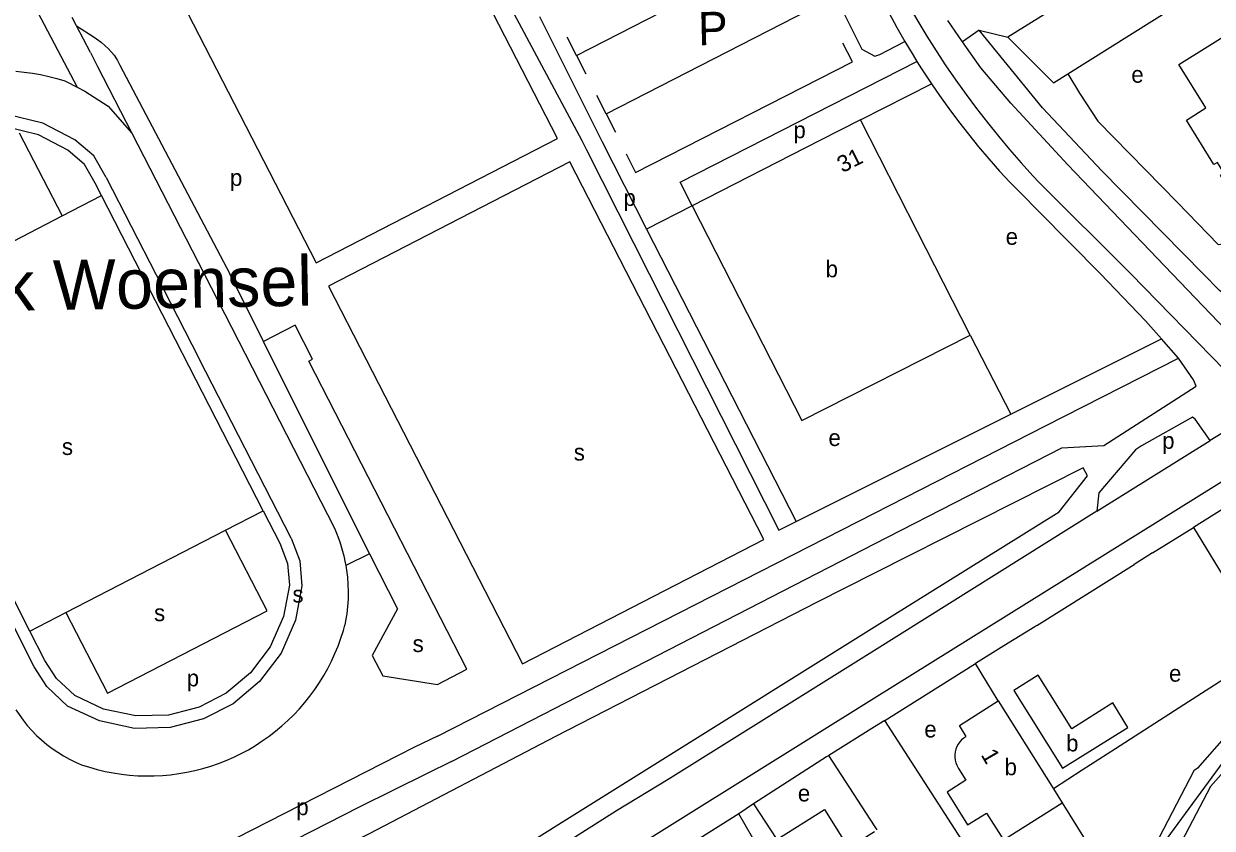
# Model space of a CAD drawing. Extents: x 158848 to 160613, y 385889 to 387762.
# Drawn here: x 159618.1 to 159904.5, y 387116.4 to 387310.2 of the extents above; entities that cross this region are included whole.
import ezdxf

# ---------------------------------------------------------------- set-up
doc = ezdxf.new("R2010")
doc.units = 0
for name, color, linetype in [('BLT_Basislijn', 7, 'Continuous'), ('BLT_Bebouwing', 7, 'Continuous'), ('BLT_Centroide', 7, 'Continuous'), ('BLT_Hoogspanningsmast_en_leidingen', 7, 'Continuous'), ('BLT_Huisnummer', 7, 'Continuous'), ('BLT_Sport_parknaam', 7, 'Continuous'), ('BLT_Tekst_parkeren', 7, 'Continuous')]:
    doc.layers.add(name, color=color, linetype=linetype)

msp = doc.modelspace()

# ---------------------------------------------------------------- linework, layer by layer
at = {"layer": 'BLT_Basislijn'}
for p, q in [((159751.28, 387302.61), (159803.28, 387329.21)), ((159619.88, 387316.11), (159630.91, 387294.99)), ((159758.44, 387288.54), (159810.48, 387315.16)), ((159630.76, 387309.75), (159629.73, 387311.77)), ((159844.35, 387305.87), (159840.78, 387310.98)), ((159848.34, 387308.65), (159844.35, 387305.87)), ((159848.34, 387308.65), (159855.27, 387306.97)), ((159751.28, 387302.61), (159749.02, 387307.04)), ((159634.14, 387303.34), (159635.87, 387299.97)), ((159751.28, 387302.61), (159753.54, 387298.17)), ((159635.87, 387299.97), (159644.12, 387283.9)), ((159628.25, 387296.36), (159630.91, 387294.99)), ((159819.77, 387287.1), (159836.83, 387295.76)), ((159758.44, 387288.54), (159756.18, 387292.97)), ((159758.44, 387288.54), (159760.69, 387284.11)), ((159616.97, 387283.94), (159627.32, 387263.93)), ((159644.12, 387283.9), (159661.52, 387250)), ((159752.58, 387282.07), (159753.71, 387279.83)), ((159757.47, 387281.77), (159768.2, 387260.77)), ((159753.71, 387279.83), (159768.79, 387250)), ((159637.95, 387273.18), (159649.96, 387249.77)), ((159858.3, 387269.48), (159855.76, 387272.05)), ((159862.71, 387272.05), (159884.93, 387250)), ((159627.32, 387263.93), (159636.8, 387268.84)), ((159675.76, 387192.89), (159636.8, 387268.84)), ((159862.75, 387264.98), (159858.3, 387269.48)), ((159779.19, 387266.39), (159768.2, 387260.77)), ((159877.59, 387250), (159862.75, 387264.98)), ((159591.19, 387245.23), (159627.32, 387263.93)), ((159768.2, 387260.77), (159804.24, 387190.31)), ((159649.96, 387249.77), (159660.26, 387229.68)), ((159661.52, 387250), (159692.96, 387188.72)), ((159675.88, 387233.68), (159667.73, 387250)), ((159619.56, 387163.91), (159580.91, 387239.91)), ((159701.43, 387182.51), (159675.88, 387233.68)), ((159846.17, 387235.22), (159855.95, 387216.16)), ((159855.95, 387216.16), (159892.27, 387234.31)), ((159896.37, 387229.67), (159892.27, 387234.31)), ((159682.5, 387186.32), (159660.26, 387229.68)), ((159864.37, 387213.35), (159896.37, 387229.67)), ((159804.24, 387190.31), (159855.95, 387216.16)), ((159823.15, 387192.34), (159864.37, 387213.35)), ((159876.74, 387192.8), (159903.99, 387209.8)), ((159620.56, 387155.33), (159598.93, 387198.22)), ((159910.62, 387195.56), (159899.97, 387188.9)), ((159666.71, 387188.22), (159675.76, 387192.89)), ((159799.49, 387180.27), (159823.15, 387192.34)), ((159876.74, 387192.8), (159823.15, 387159.28)), ((159628.23, 387168.38), (159666.71, 387188.22)), ((159676.71, 387168.83), (159666.71, 387188.22)), ((159890.12, 387182.75), (159899.97, 387188.9)), ((159721.13, 387132.51), (159823.15, 387184.9)), ((159701.43, 387182.51), (159695.68, 387179.71)), ((159890.12, 387182.75), (159885.74, 387179.97)), ((159717.79, 387138.6), (159799.49, 387180.27)), ((159862.26, 387165.23), (159885.74, 387179.97)), ((159619.56, 387163.91), (159628.23, 387168.38)), ((159628.23, 387168.38), (159638.23, 387148.99)), ((159638.23, 387148.99), (159676.71, 387168.83)), ((159854.32, 387160.35), (159847.45, 387156.09)), ((159852.91, 387147.1), (159847.45, 387156.09)), ((159897.67, 387146.13), (159881.2, 387135.53)), ((159825.6, 387142.4), (159823.15, 387140.87)), ((159852.89, 387100.09), (159825.6, 387142.4)), ((159717.79, 387138.6), (159712.26, 387135.93)), ((159823.15, 387140.87), (159812.13, 387133.98)), ((159712.26, 387135.93), (159645.73, 387102.09)), ((159823.15, 387117.04), (159812.13, 387133.98)), ((159881.2, 387135.53), (159873.2, 387130.38)), ((159721.13, 387132.51), (159715.29, 387129.57)), ((159873.2, 387130.38), (159866.25, 387125.91)), ((159793.99, 387122.27), (159790.39, 387119.92)), ((159793.99, 387122.27), (159799.55, 387113.71)), ((159790.39, 387119.92), (159778.96, 387112.63)), ((159823.79, 387116.06), (159823.15, 387117.04))]:
    msp.add_line(p, q, dxfattribs=at)
msp.add_lwpolyline([(159746.73, 387282.61), (159698.67, 387376), (159640.5, 387346.07), (159688.56, 387252.67)], close=True, dxfattribs=at)
for points in [[(159712.19, 387359.6), (159731.59, 387321.89), (159732.54, 387319.56), (159752.58, 387282.07)], [(159747.54, 387314.63), (159801.23, 387341.8), (159820.04, 387304.15), (159823.22, 387302.46), (159824.39, 387302.86), (159830.46, 387305.93)], [(159827.38, 387321.96), (159829.37, 387318.23), (159831.43, 387314.53), (159833.55, 387310.86), (159835.75, 387307.24), (159838.01, 387303.67), (159840.34, 387300.13), (159842.74, 387296.64), (159845.2, 387293.2), (159847.73, 387289.8), (159850.32, 387286.45), (159852.97, 387283.15), (159855.69, 387279.91), (159858.46, 387276.71), (159861.3, 387273.57), (159862.71, 387272.05)], [(159823.15, 387319.71), (159824.86, 387316.23), (159826.64, 387312.78), (159828.49, 387309.37), (159830.45, 387305.93)], [(159742.35, 387312), (159757.47, 387281.77)], [(159634.14, 387303.34), (159630.76, 387309.75)], [(159630.76, 387309.75), (159635.01, 387307.02), (159636.73, 387305.8), (159638.5, 387304.19), (159639.83, 387302.7), (159640.66, 387301.42), (159641.26, 387300.26), (159667.73, 387250)], [(159902.35, 387250), (159877.94, 387274.78), (159863.61, 387290), (159848.34, 387308.65)], [(159763.3, 387278.89), (159765.51, 387274.36), (159817.8, 387301.07), (159815.5, 387305.59)], [(159830.46, 387305.93), (159832.4, 387302.67), (159833.34, 387301.18)], [(159894.88, 387250), (159869.74, 387276.22), (159855.99, 387291.1), (159848.71, 387299.62), (159844.35, 387305.87)], [(159779.19, 387266.39), (159776.31, 387272.03), (159833.34, 387301.18)], [(159833.34, 387301.18), (159834.46, 387299.39), (159836.83, 387295.76)], [(159616.15, 387298.8), (159618.15, 387298.61), (159620.14, 387298.34), (159622.12, 387297.98), (159624.08, 387297.55), (159626.03, 387297.04), (159627.95, 387296.46), (159628.25, 387296.36)], [(159869.74, 387298.19), (159872.5, 387293.55), (159876.97, 387286.77), (159896.11, 387267.15), (159905.98, 387257.04), (159922.13, 387259.27)], [(159630.91, 387294.99), (159632.76, 387294.03), (159638.39, 387290.38), (159644.12, 387283.9)], [(159836.83, 387295.76), (159838.77, 387292.94), (159841.03, 387289.79), (159843.35, 387286.68), (159845.74, 387283.62), (159848.18, 387280.61), (159850.7, 387277.66), (159853.26, 387274.75), (159855.76, 387272.05)], [(159637.95, 387273.18), (159634.97, 387278.38), (159630.39, 387282.29), (159622.7, 387286.31), (159614.09, 387288.41), (159605.28, 387288.37), (159597.04, 387286.31), (159589.81, 387282.61), (159583.34, 387277.11), (159578.17, 387269.99), (159574.85, 387261.76), (159573.63, 387253.17), (159574.34, 387246.65), (159576.97, 387241.05)], [(159636.8, 387268.84), (159635.28, 387271.81), (159632.72, 387276.35), (159628.7, 387279.79), (159621.64, 387283.48), (159613.73, 387285.41), (159605.66, 387285.37), (159598.1, 387283.49), (159591.49, 387280.1), (159585.56, 387275.06), (159580.81, 387268.53), (159577.77, 387260.98), (159576.65, 387253.12), (159577.27, 387247.47), (159579.66, 387242.37), (159580.91, 387239.91)], [(159749.65, 387276.93), (159691.48, 387246.99)], [(159796.45, 387186), (159749.65, 387276.93)], [(159768.79, 387250), (159800.02, 387188.2)], [(159892.27, 387234.31), (159888.4, 387238.68), (159877.59, 387250)], [(159884.93, 387250), (159907.44, 387226.82), (159911.53, 387221.92), (159912.05, 387220.13), (159911.97, 387216.84), (159911, 387215.04), (159908.36, 387212.52), (159903.99, 387209.8)], [(159967.91, 387250), (159938.95, 387231.08), (159926.09, 387223.57), (159924.18, 387223.25), (159922.21, 387223.32), (159919, 387224.83), (159894.88, 387250)], [(159952.83, 387250), (159941, 387243.19), (159926.83, 387236.5), (159923.23, 387235.86), (159919.34, 387236.37), (159906.29, 387246.01), (159902.35, 387250)], [(159691.48, 387246.99), (159738.28, 387156.06)], [(159701.43, 387182.51), (159708.11, 387169.29), (159702.04, 387158.05), (159704.65, 387153.12), (159717.76, 387151.08), (159724.82, 387154.74), (159686.77, 387228.97), (159687.68, 387229.44), (159683.47, 387237.63), (159675.88, 387233.68)], [(159968.29, 387231.61), (159965.84, 387234.64), (159963.09, 387235.3), (159961.22, 387234.59), (159960.63, 387233.93), (159942.21, 387221.85), (159823.15, 387147.72)], [(159823.15, 387184.9), (159868.23, 387208.05), (159878.36, 387208.63), (159900.63, 387222.92), (159900.03, 387224.45), (159896.37, 387229.67)], [(159903.99, 387209.8), (159900.41, 387214.98), (159899.76, 387215.42), (159887.44, 387208.54), (159886.06, 387207.61), (159877.21, 387197.26), (159876.74, 387192.8)], [(159823.15, 387164.91), (159867.59, 387192.65), (159874.44, 387201.31), (159873.39, 387203.22), (159823.15, 387177.85)], [(159910.62, 387195.56), (159926.67, 387162.23), (159927.14, 387160.7), (159900.93, 387130.86), (159900.07, 387130.23), (159884.36, 387100), (159859.01, 387050.73), (159856.32, 387045.74), (159852.75, 387041.99)], [(159675.76, 387192.89), (159679.76, 387185.09), (159681.67, 387180.17), (159682.1, 387175), (159680.69, 387167.4), (159677.48, 387160.13), (159672.72, 387153.83), (159666.85, 387148.95), (159660.33, 387145.61), (159652.94, 387143.69), (159645.05, 387143.49), (159637.27, 387145.13), (159630.34, 387148.39), (159625.93, 387152.53), (159623.17, 387156.82), (159619.56, 387163.91)], [(159800.02, 387188.2), (159804.24, 387190.31)], [(159692.96, 387188.72), (159693.64, 387187.1), (159694.24, 387185.45), (159694.76, 387183.77), (159695.2, 387182.07), (159695.57, 387180.35), (159695.68, 387179.71)], [(159899.97, 387188.9), (159917.85, 387159.68), (159917.85, 387159.11), (159897.67, 387146.13)], [(159682.5, 387186.32), (159684.63, 387180.85), (159685.12, 387174.85), (159683.58, 387166.51), (159680.09, 387158.6), (159674.9, 387151.75), (159668.51, 387146.43), (159661.41, 387142.79), (159653.36, 387140.7), (159644.77, 387140.48), (159636.31, 387142.27), (159628.64, 387145.87), (159623.6, 387150.59), (159620.56, 387155.33)], [(159738.28, 387156.06), (159796.45, 387186)], [(159695.68, 387179.71), (159695.86, 387178.62), (159696.07, 387176.87), (159696.2, 387175.12), (159696.25, 387173.36), (159696.22, 387171.61), (159696.11, 387169.85), (159695.92, 387168.11), (159695.65, 387166.37), (159695.46, 387165.35)], [(159823.15, 387177.85), (159809.32, 387170.86), (159746.21, 387138.49), (159701.32, 387115.11), (159671.47, 387100), (159559.25, 387043.07), (159557.97, 387041.11), (159558.04, 387038.5), (159580.37, 386992.95), (159585.56, 386982.75)], [(159623.71, 387015.42), (159631.38, 387030.86), (159637.32, 387039.39), (159645.79, 387049.2), (159657.37, 387059.37), (159670.23, 387068.78), (159719.14, 387100), (159823.15, 387164.91)], [(159631.99, 387131.72), (159633.87, 387131.11), (159635.78, 387130.58), (159637.71, 387130.12), (159639.65, 387129.74), (159641.61, 387129.44), (159643.58, 387129.22), (159645.56, 387129.08), (159647.54, 387129.02), (159649.52, 387129.03), (159651.49, 387129.13), (159653.47, 387129.31), (159655.43, 387129.57), (159657.38, 387129.9), (159659.32, 387130.32), (159661.24, 387130.81), (159663.14, 387131.38), (159665.01, 387132.03), (159666.86, 387132.75), (159668.67, 387133.55), (159670.45, 387134.41), (159672.2, 387135.35), (159673.9, 387136.36), (159675.56, 387137.44), (159677.18, 387138.58), (159678.75, 387139.79), (159680.27, 387141.06), (159681.74, 387142.39), (159683.15, 387143.78), (159684.51, 387145.22), (159685.81, 387146.72), (159687.04, 387148.27), (159688.21, 387149.86), (159689.32, 387151.51), (159690.36, 387153.2), (159691.33, 387154.92), (159692.23, 387156.69), (159693.06, 387158.49), (159693.81, 387160.32), (159694.49, 387162.18), (159695.09, 387164.07), (159695.46, 387165.35)], [(159862.26, 387165.23), (159861.75, 387164.91), (159854.32, 387160.35)], [(159823.15, 387159.28), (159773.42, 387128.16), (159760.94, 387120.62), (159728.37, 387100), (159675.31, 387066.01), (159663.73, 387057.91), (159654.6, 387050.75), (159646.07, 387041.94), (159637.74, 387030.32), (159619.36, 386994.41)], [(159825.6, 387142.4), (159846.82, 387155.7), (159847.45, 387156.09)], [(159945.27, 387143.28), (159931.76, 387155.39), (159930.71, 387156.05), (159923.76, 387148.68), (159904.06, 387126.47), (159890.19, 387100), (159872.2, 387066.71), (159869.35, 387060.89), (159856.52, 387037.21)], [(159823.15, 387147.72), (159746.52, 387100), (159703.19, 387072.74), (159675.19, 387055.74), (159661.19, 387044.39), (159651.8, 387034.62), (159642.89, 387021.89), (159640.19, 387017.12), (159625.68, 386986.72)], [(159616.14, 387144.95), (159616.93, 387143.79), (159617.89, 387142.46), (159618.92, 387141.19), (159620.01, 387139.96), (159621.15, 387138.79), (159622.35, 387137.68), (159623.61, 387136.62), (159624.91, 387135.63), (159626.26, 387134.71), (159627.66, 387133.85), (159629.09, 387133.06), (159630.56, 387132.34), (159631.99, 387131.72)], [(159812.13, 387133.98), (159811.53, 387133.61), (159793.99, 387122.27)], [(159715.29, 387129.57), (159698.9, 387121.52), (159656.71, 387100), (159649.19, 387096.1)], [(159868.37, 387122.56), (159873.87, 387113.59), (159852.89, 387100.09)], [(159823.15, 387047.57), (159820.21, 387052.05), (159790.68, 387100), (159787.37, 387105.28), (159787.5, 387106.21), (159788.04, 387106.69), (159795.3, 387111.34), (159790.39, 387119.92)]]:
    msp.add_lwpolyline(points, dxfattribs=at)
at = {"layer": 'BLT_Bebouwing'}
for p, q in [((159885.95, 387326.11), (159855.27, 387306.97)), ((159852.91, 387147.1), (159866.25, 387125.91)), ((159866.25, 387125.91), (159868.37, 387122.56))]:
    msp.add_line(p, q, dxfattribs=at)
for points in [[(159922.13, 387259.27), (159915.57, 387269.74), (159910.87, 387266.8), (159906.51, 387273.78), (159907.35, 387274.29), (159905.75, 387276.83), (159904.94, 387276.32), (159898.29, 387287.01), (159903, 387289.98), (159896.43, 387300.44), (159932.54, 387322.95)], [(159869.74, 387298.19), (159900.09, 387317.29)], [(159855.27, 387306.97), (159866.25, 387295.99), (159869.74, 387298.19)], [(159819.77, 387287.1), (159809.91, 387282.09), (159779.19, 387266.39)], [(159839.72, 387247.8), (159833.49, 387260.11), (159819.77, 387287.1)], [(159779.19, 387266.39), (159788.67, 387247.8)], [(159788.67, 387247.8), (159805.59, 387214.64), (159846.17, 387235.22)], [(159846.17, 387235.22), (159839.72, 387247.8)], [(159844.92, 387138.35), (159845.22, 387138.54), (159843.6, 387141.14), (159852.91, 387147.1)], [(159844.92, 387138.35), (159844.62, 387138.12), (159844.12, 387137.69), (159843.68, 387137.2), (159843.3, 387136.66), (159842.98, 387136.08), (159842.74, 387135.46), (159842.58, 387134.82), (159842.5, 387134.17), (159842.49, 387133.51), (159842.57, 387132.85), (159842.72, 387132.21), (159842.95, 387131.59), (159843.26, 387131.01), (159843.38, 387130.8)], [(159843.38, 387130.8), (159845.13, 387127.97), (159840.59, 387125.12), (159845.52, 387117.21), (159850.12, 387120.08), (159854.18, 387113.62), (159868.37, 387122.56)], [(159799.55, 387113.71), (159811.09, 387120.94), (159816.87, 387111.72), (159823.15, 387115.66)]]:
    msp.add_lwpolyline(points, dxfattribs=at)
msp.add_lwpolyline([(159856.72, 387149.63), (159868.44, 387130.89), (159884.17, 387140.7), (159880.52, 387146.6), (159870.67, 387140.4), (159862.57, 387153.3)], close=True, dxfattribs=at)
at = {"layer": 'BLT_Hoogspanningsmast_en_leidingen'}
msp.add_line((159845.08, 387048.01), (159951.04, 387192.01), dxfattribs=at)

# ---------------------------------------------------------------- texts
at = {"layer": 'BLT_Centroide'}
for s, p in [('e', (159885.02, 387296.02)), ('p', (159803.58, 387282.66)), ('p', (159667.77, 387271.17)), ('p', (159762.61, 387266.34)), ('e', (159854.73, 387256.97)), ('b', (159811.34, 387249.16)), ('e', (159812.02, 387208.5)), ('p', (159892.46, 387207.82)), ('s', (159627.26, 387206.35)), ('s', (159750.64, 387205)), ('s', (159682.83, 387170.8)), ('s', (159649.47, 387166.32)), ('s', (159711.79, 387158.87)), ('p', (159657.35, 387150.6)), ('e', (159894.11, 387151.73)), ('e', (159835.12, 387138.29)), ('b', (159869.3, 387134.93)), ('b', (159854.48, 387129.2)), ('e', (159804.64, 387122.88)), ('p', (159683.76, 387119.57))]:
    msp.add_text(s, height=4, dxfattribs=at).set_placement(p)
at = {"layer": 'BLT_Huisnummer'}
for s, rotation, p in [('31', 26.8861, (159815.39, 387274.22)), ('1', 300.2437, (159848.66, 387134.11))]:
    msp.add_text(s, height=4, rotation=rotation, dxfattribs=at).set_placement(p)
at = {"layer": 'BLT_Sport_parknaam'}
msp.add_text('Sportpark Woensel', height=12, rotation=1, dxfattribs=at).set_placement((159551.22, 387239.96))
at = {"layer": 'BLT_Tekst_parkeren'}
msp.add_text('P', height=8, rotation=1.2719, dxfattribs=at).set_placement((159780.68, 387305.04))

doc.saveas('drawing.dxf')
